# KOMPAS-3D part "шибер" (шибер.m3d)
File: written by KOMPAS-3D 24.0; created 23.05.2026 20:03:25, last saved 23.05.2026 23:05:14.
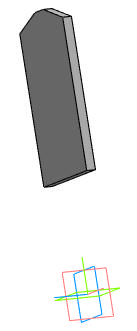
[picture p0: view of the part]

Document properties: Автор: R2D2; Полное имя файла: E:\Работа\Зайцев\GVKR1331M-1W-Fb-2P Задвижка шиберная с выдвижным штоком DN.ru Ду50-300 Ру16-10-6 с пневмоприводом\исходные материалы\DN100\шибер.m3d

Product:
- Part/product: шибер
    Масса: 1.371403
    Раздел спецификации: Прочие изделия
    Примечание: D040-08800

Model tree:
1. Эскиз:5  (with: Грань.Элемент выдавливания:1, Вершина.Элемент выдавливания:15)
2. Элемент выдавливания:6
     Расстояние 1 = 10

Referenced files in E:\Работа\Зайцев\GVKR1331M-1W-Fb-2P Задвижка шиберная с выдвижным штоком DN.ru Ду50-300 Ру16-10-6 с пневмоприводом\исходные материалы\DN100\: GVKR1331M-1W-Fb-2P Задвижка шиберная с выдвижным штоком DN.ru Ду100 Ру16.a3d
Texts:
  Затвор дисковый DN.ru Ду Ру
